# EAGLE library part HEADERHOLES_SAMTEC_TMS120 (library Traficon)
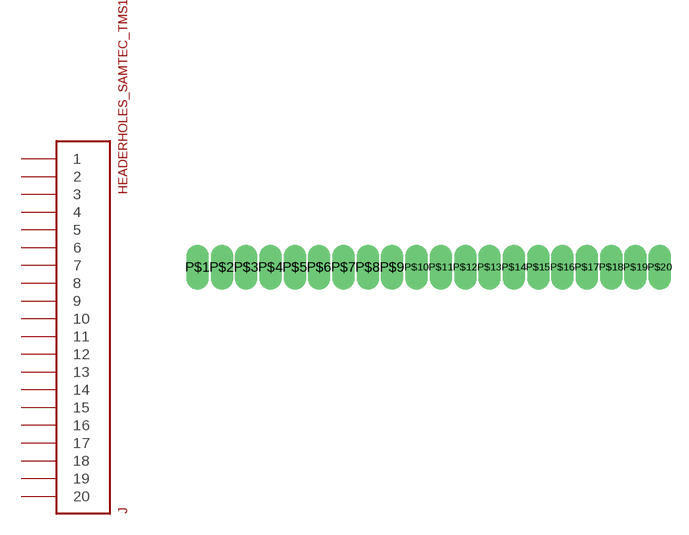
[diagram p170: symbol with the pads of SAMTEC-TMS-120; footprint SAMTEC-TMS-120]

Designator prefix J

## HEADERHOLES_SAMTEC_TMS120SA  [SAMTEC-TMS-120]
P$1  1
P$2  2
P$3  3
P$4  4
P$5  5
P$6  6
P$7  7
P$8  8
P$9  9
P$10  10
P$11  11
P$12  12
P$13  13
P$14  14
P$15  15
P$16  16
P$17  17
P$18  18
P$19  19
P$20  20

## Footprint SAMTEC-TMS-120 (pad centres in mm)
drill 0.66 pad 1.016 long: P$1 -12.065,0.25; P$2 -10.795,0.25; P$3 -9.525,0.25; P$4 -8.255,0.25; P$5 -6.985,0.25; P$6 -5.715,0.25; P$7 -4.445,0.25; P$8 -3.175,0.25; P$9 -1.905,0.25; P$10 -0.635,0.25; P$11 0.635,0.25; P$12 1.905,0.25; P$13 3.175,0.25; P$14 4.445,0.25; P$15 5.715,0.25; P$16 6.985,0.25; P$17 8.255,0.25; P$18 9.525,0.25; P$19 10.795,0.25; P$20 12.065,0.25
